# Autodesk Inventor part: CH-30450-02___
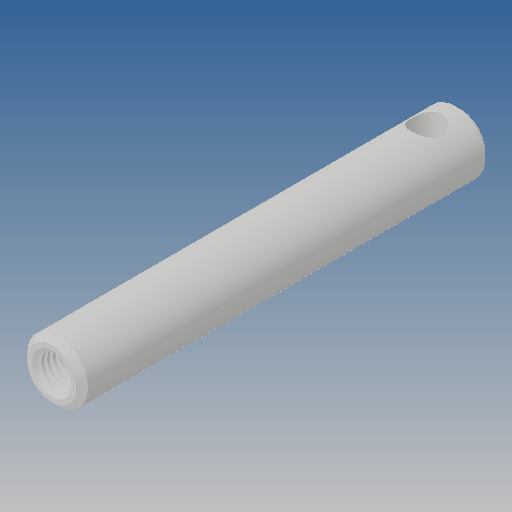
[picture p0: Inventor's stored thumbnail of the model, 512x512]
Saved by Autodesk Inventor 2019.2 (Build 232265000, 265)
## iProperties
Created: 2010-06
Part Number: CH-30450-02___
Material: Ogólny
Document SubType Name: Modeling
Designer: CADENGINEERING4
Density: 1 g/cm^3
Appearance: Domyślna
Author: CADENGINEERING4
Revision Number: ANY
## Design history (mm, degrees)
feature "NONE"
node "Bryła1"
